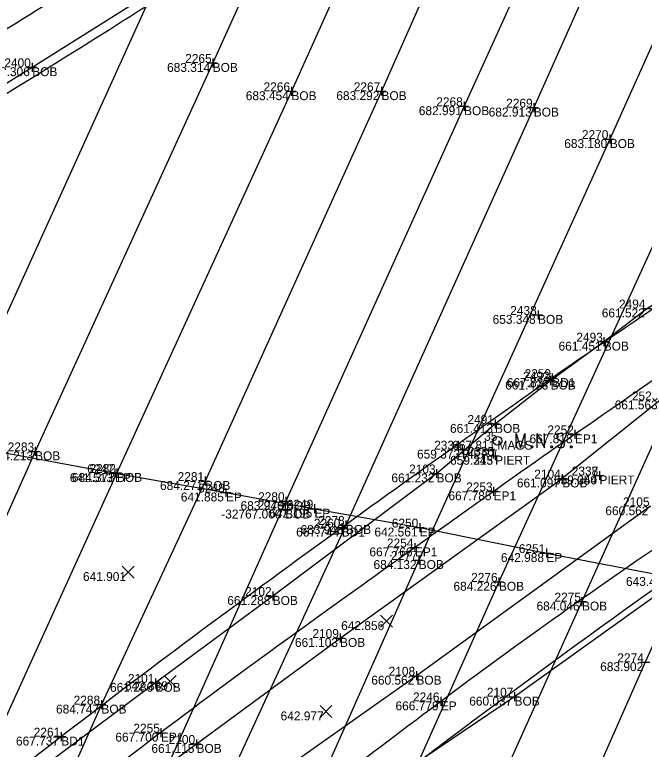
# Model space of a CAD drawing. Extents: x 2197382 to 2204062, y 634117 to 636522.
# Drawn here: x 2202630.7 to 2202701.4, y 635231.8 to 635314.3 of the extents above; entities that cross this region are included whole.
import ezdxf

# ---------------------------------------------------------------- set-up
doc = ezdxf.new("R2010")
doc.units = 0
for name, color, linetype in [('_CIVIL_CONSTRUCTION', 7, 'Continuous'), ('BR_X_SV_Bottom_of_Beam', 7, 'Continuous'), ('BR_X_SV_Bottom_of_Beam_Text', 7, 'Continuous'), ('BR_X_SV_Deck_Top', 7, 'Continuous'), ('BR_X_SV_Deck_Top_Text', 7, 'Continuous'), ('BR_X_SV_Pier_Cap_Top_Text', 7, 'Continuous'), ('GE_P_Alignment_100_Distances', 7, 'Continuous'), ('RW_X_CL_100_Curve_Data', 7, 'Continuous'), ('SH_Border', 7, 'Continuous'), ('SH_Cut_Line', 7, 'Continuous'), ('SH_Data', 7, 'Continuous'), ('SV_P_Control_Cells_Set', 7, 'Continuous')]:
    doc.layers.add(name, color=color, linetype=linetype)

msp = doc.modelspace()

# ---------------------------------------------------------------- linework, layer by layer
at = {"layer": '_CIVIL_CONSTRUCTION'}
for p, q in [((2202632.636, 635308.907), (2202632.636, 635307.907)), ((2202652.406, 635308.886), (2202653.406, 635308.886)), ((2202652.906, 635309.386), (2202652.906, 635308.386)), ((2202652.906, 635308.886), (2202652.906, 635308.886)), ((2202632.136, 635308.407), (2202633.136, 635308.407)), ((2202632.636, 635308.407), (2202632.636, 635308.407)), ((2202661.746, 635306.212), (2202661.746, 635305.212)), ((2202671.866, 635306.218), (2202671.866, 635305.218)), ((2202661.246, 635305.712), (2202662.246, 635305.712)), ((2202661.746, 635305.712), (2202661.746, 635305.712)), ((2202671.366, 635305.718), (2202672.366, 635305.718)), ((2202671.866, 635305.718), (2202671.866, 635305.718)), ((2202681.139, 635304.529), (2202681.139, 635303.529)), ((2202680.639, 635304.029), (2202681.639, 635304.029)), ((2202681.139, 635304.029), (2202681.139, 635304.029)), ((2202688.472, 635303.876), (2202689.472, 635303.876)), ((2202688.972, 635304.376), (2202688.972, 635303.376)), ((2202688.972, 635303.876), (2202688.972, 635303.876)), ((2202697.509, 635300.84), (2202697.509, 635299.84)), ((2202697.009, 635300.34), (2202698.009, 635300.34)), ((2202697.509, 635300.34), (2202697.509, 635300.34)), ((2202688.949, 635280.599), (2202689.949, 635280.599)), ((2202689.449, 635281.099), (2202689.449, 635280.099)), ((2202689.449, 635280.599), (2202689.449, 635280.599)), ((2202701.183, 635281.321), (2202702.183, 635281.321)), ((2202696.837, 635278.096), (2202696.837, 635277.096)), ((2202696.337, 635277.596), (2202697.337, 635277.596)), ((2202696.837, 635277.596), (2202696.837, 635277.596)), ((2202691.044, 635274.005), (2202691.044, 635273.005)), ((2202690.364, 635273.225), (2202691.364, 635273.225)), ((2202690.544, 635273.505), (2202691.544, 635273.505)), ((2202690.864, 635273.725), (2202690.864, 635272.725)), ((2202690.864, 635273.225), (2202690.864, 635273.225)), ((2202691.044, 635273.505), (2202691.044, 635273.505)), ((2202684.125, 635268.361), (2202685.125, 635268.361)), ((2202684.625, 635268.861), (2202684.625, 635267.861)), ((2202684.625, 635268.361), (2202684.625, 635268.361)), ((2202693.595, 635267.692), (2202693.595, 635266.692)), ((2202693.095, 635267.192), (2202694.095, 635267.192)), ((2202693.595, 635267.192), (2202693.595, 635267.192)), ((2202632.96, 635265.777), (2202632.96, 635264.777)), ((2202680.923, 635265.97), (2202680.923, 635264.97)), ((2202632.46, 635265.277), (2202633.46, 635265.277)), ((2202632.96, 635265.277), (2202632.96, 635265.277)), ((2202680.423, 635265.47), (2202681.423, 635265.47)), ((2202680.923, 635265.47), (2202680.923, 635265.47)), ((2202684.636, 635265.277), (2202684.636, 635264.277)), ((2202684.638, 635265.277), (2202684.638, 635264.277)), ((2202684.136, 635264.777), (2202685.136, 635264.777)), ((2202684.138, 635264.777), (2202685.138, 635264.777)), ((2202684.636, 635264.777), (2202684.636, 635264.777)), ((2202684.638, 635264.777), (2202684.638, 635264.777)), ((2202641.924, 635263.324), (2202641.924, 635262.324)), ((2202642.152, 635263.355), (2202642.152, 635262.355)), ((2202678.051, 635263.299), (2202678.051, 635262.299)), ((2202641.424, 635262.824), (2202642.424, 635262.824)), ((2202641.652, 635262.855), (2202642.652, 635262.855)), ((2202641.924, 635262.824), (2202641.924, 635262.824)), ((2202642.152, 635262.855), (2202642.152, 635262.855)), ((2202652.069, 635262.442), (2202652.069, 635261.442)), ((2202677.551, 635262.799), (2202678.551, 635262.799)), ((2202678.051, 635262.799), (2202678.051, 635262.799)), ((2202692.169, 635262.728), (2202692.169, 635261.728)), ((2202695.854, 635262.568), (2202696.854, 635262.568)), ((2202695.857, 635262.569), (2202696.857, 635262.569)), ((2202696.354, 635263.068), (2202696.354, 635262.068)), ((2202696.354, 635262.568), (2202696.354, 635262.568)), ((2202696.357, 635263.069), (2202696.357, 635262.069)), ((2202696.357, 635262.569), (2202696.357, 635262.569)), ((2202651.569, 635261.942), (2202652.569, 635261.942)), ((2202652.069, 635261.942), (2202652.069, 635261.942)), ((2202691.669, 635262.228), (2202692.669, 635262.228)), ((2202692.169, 635262.228), (2202692.169, 635262.228)), ((2202654.395, 635261.157), (2202654.395, 635260.157)), ((2202683.959, 635260.792), (2202684.959, 635260.792)), ((2202684.459, 635261.292), (2202684.459, 635260.292)), ((2202684.459, 635260.792), (2202684.459, 635260.792)), ((2202653.895, 635260.657), (2202654.895, 635260.657)), ((2202654.395, 635260.657), (2202654.395, 635260.657)), ((2202661.138, 635260.186), (2202661.138, 635259.186)), ((2202660.638, 635259.686), (2202661.638, 635259.686)), ((2202661.058, 635259.241), (2202661.058, 635258.241)), ((2202661.138, 635259.686), (2202661.138, 635259.686)), ((2202664.333, 635259.343), (2202664.333, 635258.343)), ((2202660.558, 635258.741), (2202661.558, 635258.741)), ((2202661.058, 635258.741), (2202661.058, 635258.741)), ((2202663.833, 635258.843), (2202664.833, 635258.843)), ((2202664.333, 635258.843), (2202664.333, 635258.843)), ((2202667.875, 635257.509), (2202667.875, 635256.509)), ((2202666.904, 635256.715), (2202667.904, 635256.715)), ((2202667.375, 635257.009), (2202668.375, 635257.009)), ((2202667.404, 635257.215), (2202667.404, 635256.215)), ((2202667.404, 635256.715), (2202667.404, 635256.715)), ((2202667.875, 635257.009), (2202667.875, 635257.009)), ((2202675.656, 635256.722), (2202676.656, 635256.722)), ((2202676.156, 635257.222), (2202676.156, 635256.222)), ((2202676.156, 635256.722), (2202676.156, 635256.722)), ((2202675.116, 635254.49), (2202676.116, 635254.49)), ((2202675.616, 635254.99), (2202675.616, 635253.99)), ((2202675.616, 635254.49), (2202675.616, 635254.49)), ((2202690.385, 635254.356), (2202690.385, 635253.356)), ((2202676.043, 635253.572), (2202676.043, 635252.572)), ((2202689.885, 635253.856), (2202690.885, 635253.856)), ((2202690.385, 635253.856), (2202690.385, 635253.856)), ((2202675.543, 635253.072), (2202676.543, 635253.072)), ((2202676.043, 635253.072), (2202676.043, 635253.072)), ((2202685.056, 635251.13), (2202685.056, 635250.13)), ((2202684.556, 635250.63), (2202685.556, 635250.63)), ((2202685.056, 635250.63), (2202685.056, 635250.63)), ((2202659.643, 635249.537), (2202659.643, 635248.537)), ((2202659.143, 635249.037), (2202660.143, 635249.037)), ((2202659.643, 635249.037), (2202659.643, 635249.037)), ((2202693.886, 635248.414), (2202694.886, 635248.414)), ((2202694.386, 635248.914), (2202694.386, 635247.914)), ((2202694.386, 635248.414), (2202694.386, 635248.414)), ((2202666.709, 635244.323), (2202667.709, 635244.323)), ((2202667.209, 635244.823), (2202667.209, 635243.823)), ((2202667.209, 635244.323), (2202667.209, 635244.323)), ((2202701.002, 635241.604), (2202702.002, 635241.604)), ((2202675.791, 635240.59), (2202675.791, 635239.59)), ((2202646.481, 635239.785), (2202646.481, 635238.785)), ((2202675.291, 635240.09), (2202676.291, 635240.09)), ((2202675.791, 635240.09), (2202675.791, 635240.09)), ((2202645.981, 635239.285), (2202646.981, 635239.285)), ((2202646.481, 635239.285), (2202646.481, 635239.285)), ((2202678.527, 635237.704), (2202678.527, 635236.704)), ((2202686.316, 635237.736), (2202687.316, 635237.736)), ((2202686.816, 635238.236), (2202686.816, 635237.236)), ((2202686.816, 635237.736), (2202686.816, 635237.736)), ((2202640.406, 635237.344), (2202640.406, 635236.344)), ((2202678.027, 635237.204), (2202679.027, 635237.204)), ((2202678.527, 635237.204), (2202678.527, 635237.204)), ((2202639.906, 635236.844), (2202640.906, 635236.844)), ((2202640.406, 635236.844), (2202640.406, 635236.844)), ((2202635.903, 635233.752), (2202635.903, 635232.752)), ((2202646.588, 635233.693), (2202647.588, 635233.693)), ((2202647.088, 635234.193), (2202647.088, 635233.193)), ((2202647.088, 635233.693), (2202647.088, 635233.693)), ((2202635.403, 635233.252), (2202636.403, 635233.252)), ((2202635.903, 635233.252), (2202635.903, 635233.252)), ((2202651.091, 635232.928), (2202651.091, 635231.928)), ((2202650.591, 635232.428), (2202651.591, 635232.428)), ((2202651.091, 635232.428), (2202651.091, 635232.428))]:
    msp.add_line(p, q, dxfattribs=at)
at = {"layer": 'BR_X_SV_Bottom_of_Beam'}
for points in [[(2202550.738, 635261.3), (2202572.992, 635273.891), (2202594.556, 635285.879), (2202604.099, 635291.315), (2202615.232, 635297.565), (2202632.636, 635308.407), (2202649.916, 635319.32), (2202686.545, 635342.9), (2202715.55, 635365.054), (2202734.551, 635379.543), (2202765.2, 635403.192), (2202782.887, 635418.269), (2202797.351, 635430.625), (2202810.639, 635442.162), (2202822.488, 635452.15)], [(2202698.738, 635432.336), (2202647.005, 635318.77), (2202622.897, 635265.637), (2202604.224, 635223.888), (2202566.194, 635137.247)], [(2202700.297, 635413.559), (2202652.906, 635308.886), (2202632.96, 635265.277), (2202616.353, 635228.13), (2202571.256, 635128.111)], [(2202692.588, 635374.159), (2202661.746, 635305.712), (2202642.152, 635262.855), (2202627.428, 635230.558), (2202583.755, 635133.025)], [(2202740.069, 635349.468), (2202715.953, 635296.202), (2202694.386, 635248.414), (2202667.266, 635188.144), (2202637.877, 635121.952)], [(2202678.051, 635262.799), (2202684.625, 635268.361), (2202690.864, 635273.225), (2202696.837, 635277.596), (2202701.683, 635281.321), (2202707.618, 635285.11), (2202713.068, 635288.536), (2202720.633, 635293.164), (2202730.302, 635299.387), (2202737.074, 635303.557), (2202743.539, 635307.672), (2202751.511, 635312.627), (2202759.153, 635317.524), (2202767.171, 635322.552), (2202773.549, 635326.537), (2202779.182, 635329.627), (2202785.667, 635333.317), (2202791.954, 635336.798), (2202806.729, 635344.852)], [(2202811.504, 635338.061), (2202803.455, 635333.789), (2202794.807, 635329.254), (2202786.19, 635324.735), (2202778.702, 635319.917), (2202771.663, 635315.498), (2202764.051, 635310.711), (2202755.681, 635305.423), (2202747.659, 635300.235), (2202741.303, 635296.04), (2202731.701, 635290.077), (2202723.255, 635284.893), (2202714.676, 635279.527), (2202703.12, 635270.999), (2202692.169, 635262.228)], [(2202684.722, 635334.745), (2202671.866, 635305.718), (2202652.069, 635261.942), (2202640.406, 635236.844), (2202595.668, 635136.573)], [(2202693.73, 635331.743), (2202681.139, 635304.029), (2202661.138, 635259.686), (2202647.23, 635228.581)], [(2202700.87, 635330.601), (2202688.972, 635303.876), (2202667.875, 635257.009), (2202653.513, 635225.855), (2202612.344, 635134.534)], [(2202709.688, 635327.457), (2202697.509, 635300.34), (2202676.043, 635253.072), (2202658.006, 635212.414), (2202623.889, 635137.034)], [(2202715.96, 635318.345), (2202706.84, 635298.156), (2202685.056, 635250.63), (2202665.977, 635208.006), (2202633.465, 635136.302)], [(2202729.105, 635302.144), (2202726.598, 635297.416), (2202701.502, 635241.604), (2202672.251, 635175.36), (2202647.787, 635122.43)], [(2202678.051, 635262.799), (2202659.643, 635249.037), (2202646.481, 635239.285), (2202623.612, 635222.241), (2202606.613, 635208.622)], [(2202617.23, 635206.4), (2202629.372, 635216.615), (2202651.091, 635232.428), (2202667.209, 635244.323), (2202692.169, 635262.228)], [(2202702.088, 635259.114), (2202675.791, 635240.09), (2202655.255, 635225.566), (2202632.367, 635208.026), (2202627.431, 635204.036)], [(2202711.743, 635255.569), (2202686.816, 635237.736), (2202670.675, 635226.826), (2202658.188, 635218.045), (2202639.19, 635203.004)]]:
    msp.add_lwpolyline(points, dxfattribs=at)
at = {"layer": 'BR_X_SV_Deck_Top'}
for points in [[(2202430.051, 635233.588), (2202439.74, 635238.507), (2202466.339, 635247.691), (2202507.168, 635268.028), (2202543.723, 635286.397), (2202574.877, 635303.715), (2202604.911, 635320.157), (2202634.127, 635339.4), (2202663.018, 635358.594), (2202692.445, 635376.507), (2202729.246, 635404.451), (2202755.806, 635426.417), (2202769.739, 635438.84)], [(2202458.051, 635216.681), (2202477.116, 635219.979), (2202511.723, 635243.78), (2202554.955, 635262.299), (2202588.014, 635280.674), (2202608.342, 635292.387), (2202640.833, 635312.137), (2202668.147, 635329.948), (2202698.573, 635351.315), (2202722.135, 635368.649), (2202754.604, 635393.426), (2202777.494, 635412.293), (2202789.607, 635422.635)], [(2202895.365, 635391.811), (2202885.347, 635387.334), (2202865.192, 635377.205), (2202839.037, 635363.762), (2202813.103, 635349.723), (2202789.18, 635336.138), (2202762.388, 635320.287), (2202740.668, 635306.565), (2202716.628, 635290.831), (2202693.394, 635275.343), (2202664.567, 635254.787), (2202633.536, 635231.765), (2202595.89, 635201.643), (2202569.397, 635178.622), (2202555.165, 635165.675)], [(2202923.181, 635376.197), (2202906.167, 635369.085), (2202881.487, 635355.934), (2202846.739, 635338.13), (2202819.013, 635322.649), (2202790.142, 635306.09), (2202754.022, 635283.778), (2202709.422, 635255.583), (2202663.285, 635220.884), (2202620.566, 635187.914), (2202595.285, 635167.396), (2202582.509, 635156.81)]]:
    msp.add_open_spline(points, degree=3, dxfattribs=at)
at = {"layer": 'GE_P_Alignment_100_Distances'}
msp.add_lwpolyline([(2202498.738, 635292.198), (2202504.316, 635290.969), (2202510.464, 635289.53), (2202518.118, 635287.829), (2202527.68, 635285.66), (2202535.473, 635284.068), (2202543.688, 635282.23), (2202552.965, 635280.17), (2202564.038, 635277.917), (2202577.102, 635275.328), (2202589.148, 635272.888), (2202599.874, 635270.951), (2202613.435, 635268.276), (2202628.15, 635265.389), (2202641.924, 635262.824), (2202654.395, 635260.657), (2202664.333, 635258.843), (2202676.156, 635256.722), (2202690.385, 635253.856), (2202704.424, 635251.17), (2202718.674, 635248.712), (2202737.349, 635245.359), (2202761.228, 635240.853), (2202781.345, 635237.182)], dxfattribs=at)
for points in [[(2202483.163, 635252.761), (2202495.402, 635258.227), (2202515.209, 635267.824), (2202539.505, 635280.183), (2202556.272, 635289.074), (2202570.794, 635297.089), (2202585.76, 635305.335), (2202607.83, 635319.01), (2202630.778, 635332.646), (2202656.431, 635348.815), (2202675.69, 635362.468), (2202698.981, 635379.185), (2202729.904, 635401.353), (2202753.674, 635420.874), (2202767.823, 635433.185)], [(2202457.668, 635223.282), (2202466.48, 635226.872), (2202500.455, 635242.355), (2202539.476, 635261.183), (2202573.06, 635279.52), (2202585.609, 635286.631), (2202599.84, 635294.842), (2202617.618, 635305.231), (2202642.294, 635320.395), (2202667.372, 635336.77), (2202691.723, 635353.633), (2202713.413, 635369.403), (2202739.641, 635388.973), (2202758.657, 635404.276), (2202770.061, 635413.813)], [(2202926.993, 635398.223), (2202911.054, 635391.267), (2202884.78, 635379.221), (2202850.251, 635362.173), (2202828.215, 635350.038), (2202808.09, 635339.198), (2202790.855, 635329.045), (2202764, 635313.325), (2202738.781, 635297.635), (2202713.051, 635280.577), (2202697.019, 635269.602), (2202684.529, 635260.864), (2202668.986, 635249.754), (2202642.65, 635230.806), (2202596.561, 635193.887), (2202560.681, 635163.156), (2202538.312, 635142.813)], [(2202919.499, 635378.368), (2202901.447, 635370.678), (2202875.936, 635356.879), (2202844.592, 635341.598), (2202825.856, 635330.823), (2202809.466, 635322.019), (2202780.051, 635304.409), (2202746.062, 635282.999), (2202707.717, 635258.176), (2202682.244, 635240.209), (2202658.947, 635222.257), (2202614.143, 635189.251), (2202577.354, 635157.516), (2202549.508, 635131.427)]]:
    msp.add_open_spline(points, degree=3, dxfattribs=at)
at = {"layer": 'RW_X_CL_100_Curve_Data'}
for p, q in [((2202642.751, 635251.056), (2202644.085, 635252.392)), ((2202642.751, 635252.392), (2202644.085, 635251.056)), ((2202671.773, 635245.546), (2202673.107, 635246.88)), ((2202671.773, 635246.88), (2202673.107, 635245.546)), ((2202647.461, 635238.796), (2202648.795, 635240.132)), ((2202647.461, 635240.132), (2202648.795, 635238.796)), ((2202664.965, 635235.407), (2202666.299, 635236.742)), ((2202664.965, 635236.742), (2202666.299, 635235.407))]:
    msp.add_line(p, q, dxfattribs=at)
at = {"layer": 'SV_P_Control_Cells_Set'}
for points in [[(2202686.984, 635265.669), (2202686.984, 635267.269), (2202687.491, 635265.669), (2202687.976, 635267.269), (2202687.976, 635265.669)], [(2202689.354, 635265.669), (2202689.354, 635267.269), (2202690.181, 635265.669), (2202690.181, 635267.269)], [(2202692.331, 635267.156), (2202692.309, 635267.181), (2202692.275, 635267.206), (2202692.176, 635267.244), (2202692.055, 635267.269), (2202691.967, 635267.269), (2202691.934, 635267.269), (2202691.79, 635267.232), (2202691.669, 635267.156), (2202691.592, 635267.055), (2202691.57, 635266.954), (2202691.57, 635266.879), (2202691.592, 635266.778), (2202691.68, 635266.69), (2202692.287, 635266.312), (2202692.342, 635266.262), (2202692.364, 635266.211), (2202692.386, 635266.136), (2202692.386, 635266.06), (2202692.375, 635265.984), (2202692.364, 635265.934), (2202692.342, 635265.871), (2202692.32, 635265.821), (2202692.297, 635265.783), (2202692.264, 635265.745), (2202692.231, 635265.72), (2202692.187, 635265.695), (2202692.154, 635265.682), (2202692.055, 635265.669), (2202691.901, 635265.669), (2202691.802, 635265.695), (2202691.658, 635265.783), (2202691.57, 635265.858)], [(2202688.748, 635265.884), (2202688.803, 635265.884), (2202688.836, 635265.858), (2202688.869, 635265.808), (2202688.869, 635265.745), (2202688.836, 635265.695), (2202688.803, 635265.669), (2202688.748, 635265.669), (2202688.715, 635265.695), (2202688.682, 635265.745), (2202688.682, 635265.808), (2202688.715, 635265.858), (2202688.748, 635265.884)], [(2202690.964, 635265.884), (2202691.019, 635265.884), (2202691.052, 635265.858), (2202691.085, 635265.808), (2202691.085, 635265.745), (2202691.052, 635265.695), (2202691.019, 635265.669), (2202690.964, 635265.669), (2202690.931, 635265.695), (2202690.898, 635265.745), (2202690.898, 635265.808), (2202690.931, 635265.858), (2202690.964, 635265.884)], [(2202693.146, 635265.884), (2202693.201, 635265.884), (2202693.235, 635265.858), (2202693.267, 635265.808), (2202693.267, 635265.745), (2202693.235, 635265.695), (2202693.201, 635265.669), (2202693.146, 635265.669), (2202693.113, 635265.695), (2202693.08, 635265.745), (2202693.08, 635265.808), (2202693.113, 635265.858), (2202693.146, 635265.884)]]:
    msp.add_lwpolyline(points, dxfattribs=at)
msp.add_circle((2202684.894, 635266.469), 0.497, dxfattribs=at)

# ---------------------------------------------------------------- texts
at = {"layer": 'BR_X_SV_Bottom_of_Beam_Text'}
for s, p in [('2265', (2202649.817, 635308.886)), ('2400', (2202629.504, 635308.407)), ('683.314', (2202647.784, 635307.886)), ('BOB', (2202652.906, 635307.886)), ('658.306', (2202627.532, 635307.407)), ('BOB', (2202632.636, 635307.407)), ('2266', (2202658.623, 635305.712)), ('2267', (2202668.751, 635305.718)), ('683.454', (2202656.624, 635304.712)), ('BOB', (2202661.746, 635304.712)), ('683.292', (2202666.793, 635304.718)), ('BOB', (2202671.866, 635304.718)), ('2268', (2202678.02, 635304.029)), ('2269', (2202685.87, 635303.876)), ('682.991', (2202676.057, 635303.029)), ('BOB', (2202681.139, 635303.029)), ('682.913', (2202683.908, 635302.876)), ('BOB', (2202688.972, 635302.876)), ('2270', (2202694.377, 635300.34)), ('683.180', (2202692.395, 635299.34)), ('BOB', (2202697.509, 635299.34)), ('2494', (2202698.542, 635281.321)), ('2438', (2202686.33, 635280.599)), ('653.348', (2202684.349, 635279.599)), ('BOB', (2202689.449, 635279.599)), ('661.522', (2202696.61, 635280.321)), ('2493', (2202693.754, 635277.596)), ('661.451', (2202691.755, 635276.596)), ('BOB', (2202696.837, 635276.596)), ('2492', (2202687.772, 635273.225)), ('661.428', (2202685.764, 635272.225)), ('BOB', (2202690.864, 635272.225)), ('2520', (2202699.988, 635270.999)), ('661.563', (2202698.056, 635269.999)), ('2491', (2202681.525, 635268.361)), ('661.413', (2202679.561, 635267.361)), ('BOB', (2202684.625, 635267.361)), ('2283', (2202629.877, 635265.277)), ('684.213', (2202627.896, 635264.277)), ('BOB', (2202632.96, 635264.277)), ('2282', (2202639.06, 635262.855)), ('2103', (2202674.968, 635262.799)), ('2104', (2202689.028, 635262.228)), ('684.373', (2202637.088, 635261.855)), ('BOB', (2202642.152, 635261.855)), ('2281', (2202648.969, 635261.942)), ('661.232', (2202672.978, 635261.799)), ('BOB', (2202678.051, 635261.799)), ('684.271', (2202646.987, 635260.942)), ('BOB', (2202652.069, 635260.942)), ('661.097', (2202687.073, 635261.228)), ('BOB', (2202692.169, 635261.228)), ('2280', (2202658.006, 635259.686)), ('2105', (2202698.999, 635259.114)), ('683.946', (2202656.034, 635258.686)), ('2279', (2202657.956, 635258.741)), ('BOB', (2202661.138, 635258.686)), ('660.562', (2202697.015, 635258.114)), ('-32767.000', (2202653.866, 635257.741)), ('BOB', (2202661.058, 635257.741)), ('2278', (2202664.756, 635257.009)), ('683.948', (2202662.775, 635256.009)), ('BOB', (2202667.875, 635256.009)), ('2277', (2202672.928, 635253.072)), ('684.132', (2202670.97, 635252.072)), ('BOB', (2202676.043, 635252.072)), ('2276', (2202681.933, 635250.63)), ('2102', (2202656.551, 635249.037)), ('684.226', (2202679.952, 635249.63)), ('BOB', (2202685.056, 635249.63)), ('2275', (2202691.297, 635248.414)), ('661.288', (2202654.543, 635248.037)), ('BOB', (2202659.643, 635248.037)), ('684.046', (2202689.282, 635247.414)), ('BOB', (2202694.386, 635247.414)), ('2109', (2202664.107, 635244.323)), ('661.103', (2202662.145, 635243.323)), ('BOB', (2202667.209, 635243.323)), ('2274', (2202698.361, 635241.604)), ('2108', (2202672.672, 635240.09)), ('683.902', (2202696.429, 635240.604)), ('2101', (2202643.381, 635239.285)), ('660.562', (2202670.718, 635239.09)), ('BOB', (2202675.791, 635239.09)), ('661.286', (2202641.377, 635238.285)), ('BOB', (2202646.481, 635238.285)), ('2107', (2202683.701, 635237.736)), ('2288', (2202637.287, 635236.844)), ('660.037', (2202681.72, 635236.736)), ('BOB', (2202686.816, 635236.736)), ('684.747', (2202635.31, 635235.844)), ('BOB', (2202640.406, 635235.844)), ('2100', (2202647.959, 635232.428)), ('661.115', (2202646.021, 635231.428)), ('BOB', (2202651.091, 635231.428))]:
    msp.add_text(s, height=1, dxfattribs=at).set_placement(p)
at = {"layer": 'BR_X_SV_Deck_Top_Text'}
for s, p in [('2259', (2202687.942, 635273.505)), ('667.837', (2202685.948, 635272.505)), ('BD1', (2202691.044, 635272.505)), ('2260', (2202664.272, 635256.715)), ('667.744', (2202662.282, 635255.715)), ('BD1', (2202667.404, 635255.715)), ('2261', (2202632.803, 635233.252)), ('667.737', (2202630.807, 635232.252)), ('BD1', (2202635.903, 635232.252))]:
    msp.add_text(s, height=1, dxfattribs=at).set_placement(p)
at = {"layer": 'BR_X_SV_Pier_Cap_Top_Text'}
for s, p in [('2334', (2202677.782, 635265.47)), ('2336', (2202681.515, 635264.777)), ('2335', (2202681.547, 635264.777)), ('659.373', (2202675.859, 635264.47)), ('PIERT', (2202680.923, 635264.47)), ('659.345', (2202679.566, 635263.777)), ('659.213', (2202679.574, 635263.777)), ('PIERT', (2202684.636, 635263.777)), ('PIERT', (2202684.638, 635263.777)), ('2338', (2202693.235, 635262.568)), ('2337', (2202693.242, 635262.569)), ('659.244', (2202691.235, 635261.569)), ('659.050', (2202691.24, 635261.568)), ('PIERT', (2202696.354, 635261.568)), ('PIERT', (2202696.357, 635261.569))]:
    msp.add_text(s, height=1, dxfattribs=at).set_placement(p)
at = {"layer": 'SH_Border'}
for s, p in [('EP1', (2202693.595, 635266.192)), ('MAGS', (2202684.894, 635265.47)), ('EP', (2202641.924, 635261.824)), ('EP1', (2202684.459, 635259.792)), ('EP', (2202654.395, 635259.657)), ('EP', (2202664.333, 635257.843)), ('EP', (2202676.156, 635255.722)), ('EP1', (2202675.616, 635253.49)), ('EP', (2202690.385, 635252.856)), ('EP', (2202678.527, 635236.204)), ('EP1', (2202647.088, 635232.693))]:
    msp.add_text(s, height=1, dxfattribs=at).set_placement(p)
at = {"layer": 'SH_Cut_Line'}
for s, p in [('2252', (2202690.503, 635267.192)), ('35', (2202683.401, 635266.47)), ('6247', (2202638.809, 635262.824)), ('6248', (2202651.276, 635260.657)), ('2253', (2202681.376, 635260.792)), ('6249', (2202661.231, 635258.843)), ('6250', (2202673.024, 635256.722)), ('2254', (2202672.475, 635254.49)), ('6251', (2202687.285, 635253.856)), ('2246', (2202675.404, 635237.204)), ('2255', (2202643.999, 635233.693))]:
    msp.add_text(s, height=1, dxfattribs=at).set_placement(p)
at = {"layer": 'SH_Data'}
for s, p in [('667.818', (2202688.495, 635266.192)), ('667.811', (2202679.812, 635265.47)), ('641.513', (2202636.86, 635261.824)), ('667.785', (2202679.389, 635259.792)), ('641.885', (2202649.325, 635259.657)), ('642.195', (2202659.263, 635257.843)), ('642.561', (2202671.074, 635255.722)), ('667.766', (2202670.512, 635253.49)), ('642.988', (2202685.285, 635252.856)), ('641.901', (2202638.336, 635250.724)), ('643.427', (2202699.328, 635250.17)), ('642.856', (2202667.336, 635245.213)), ('642.389', (2202643.044, 635238.464)), ('666.779', (2202673.443, 635236.204)), ('642.977', (2202660.536, 635235.075)), ('667.700', (2202641.974, 635232.693))]:
    msp.add_text(s, height=1, dxfattribs=at).set_placement(p)

doc.saveas('drawing.dxf')
